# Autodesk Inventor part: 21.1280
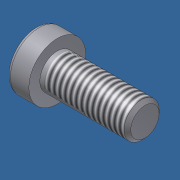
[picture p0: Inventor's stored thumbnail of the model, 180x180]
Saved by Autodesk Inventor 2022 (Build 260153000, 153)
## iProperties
Created: 2006-02
Part Number: 21.1280
Material: Steel, Mild
Description: M8X22 SHCS
Document SubType Name: Modeling
Standard: DIN 7984
Designer: Andy Moles
Standards Organization: DIN
Language: en-US
Size Designation: M8 x 20
Categories: <MemberInstance><Categories><Category DisplayName="Fasteners" InternalName="e4da775c-781d-43d5-af7c-5136215cf5a6" Mnemonic="FSTN"><Category DisplayName="Bolts"
Density: 7.85 g/cm^3
Mass: 13.0366 g
Surface Area: 10.6794 cm^2
Volume: 1.66071 cm^3
Vendor: S
Appearance: Zinc
Author: Andy Moles
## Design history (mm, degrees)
sketch "Sketch1"
  geometry: L1 (0.467, 0)-(22, 0); L2 (22, 0)-(22, 4); L3 (22, 4)-(1, 4); L4 (1, 4)-(0.233, 4); L5 (0.233, 4)-(0, 4); L6 (0, 4)-(0, 6.5); L7 (0, 6.5)-(-5, 6.5); L8 (-5, 6.5)-(-5, 2.887); L9 (-5, 2.887)-(-1.2, 2.887); L10 (-1.2, 2.887)-(0.467, 0); L11 (-7.5, 0)-(27.5, 0) reference; L12 (0, -0.65)-(0, 8.45) reference; L13 (1, 4)-(0, 4)
  constraints: 22 end point, 6 parallel, 2 collinear, 2 perpendicular, 1 horizontal, 1 point on line
  dimensions: "d1" = 21 distance from line of L3.end L2 (= GEL); "d2" = 0.76691 distance of L4.end L3.end (computed from GAL); "d3" = 5 distance between parallel lines of L8 L6 (= KOH); "d4" = 3.8 distance of L8.end L9.end (= INTI); "d5" = 60 deg angle of L10 L1; "d6" = 8 diameter of L3 L1 (= GD); "d7" = 8 diameter of L5 L1 (= BDM); "d8" = 5.7735 diameter of L9 L1 (= 1.1547 x SW); "d9" = 13 diameter of L7 L1 (= KOD); "d26" = 22 distance between parallel lines of L12 L2 (= NLG)
revolve "Body" sketch "Sketch1" stored, may be unused: angle "d10" = 90 deg
sketch "Sketch2"
  geometry: L1 (0, -7.8)-(0, 10.4) reference; L2 (-7.8, 0)-(10.4, 0) reference; L3 (2.887, 0)-(1.443, -2.5); L4 (1.443, -2.5)-(-1.443, -2.5); L5 (-1.443, -2.5)-(-2.887, 0); L6 (-2.887, 0)-(-1.443, 2.5); L7 (-1.443, 2.5)-(1.443, 2.5); L8 (1.443, 2.5)-(2.887, 0); 2 further points
  constraints: 12 end point, 1 coincident, 1 horizontal alignment, 1 point on line, 12 other
extrude "Slot" join sketch "Sketch2" stored distance "d11" = 10; taper "d12" = 0 deg
workplane "Work Plane1"
body "Solid1"
fillet "Fillet1" dims "d17" = 0.8 (= RR)
feature "Thread" dims "d13" = 22, "d14" = 0
chamfer "Chamfer1" distance "d15" = 0.76681 (= -0.5 x SPD + 0.5 x GD); stored, may be unused: second distance "d16" = 0.76681 (= GUL), angle "d27" = 45 deg
other parameters: "GD" = 8 (= NND) [user parameter; used in 2 equation terms], "NLG" = 22 [user parameter; used in 1 equation term], "GEL" = 21 [user parameter; used in 1 equation term], "KOD" = 13 [user parameter; used in 1 equation term], "KOH" = 5 [user parameter; used in 1 equation term], "INTI" = 3.8 [user parameter; used in 1 equation term], "GAL" = 0.76681 (= 0.61345 x PTC) [user parameter; used in 1 equation term], "GUL" = 0.76681 (= 0.61345 x PTC) [user parameter; used in 1 equation term], "BDM" = 8 (= NND) [user parameter; used in 1 equation term], "SW" = 5 [user parameter; used in 2 equation terms], "RR" = 0.8 [user parameter; used in 1 equation term], "SPD" = 6.46637 (= NND - 1.2269 x PTC) [user parameter; used in 1 equation term], "d19" = 0, "d28" = 0, "d29" = 0, "TOA" = 30 deg [user parameter], "GD1" = 6.46637 (= THREADDIA - 1.2269 x PTC) [user parameter], "THREADDIA" = 8 [user parameter; used in 1 equation term], "FAWI" = 45 deg [user parameter], "ANG" = 120 deg [user parameter], "TPU" = 8 (computed from PTC) [user parameter], "PTC" = 1.25 [user parameter; used in 5 equation terms], "NND" = 8 [user parameter; used in 3 equation terms], "E0" = 5.775 (= 1.155 x SW) [user parameter]
